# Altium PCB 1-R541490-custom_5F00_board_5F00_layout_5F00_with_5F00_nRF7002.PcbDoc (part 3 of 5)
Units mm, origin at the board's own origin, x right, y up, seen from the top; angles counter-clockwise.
Board outline 180 x 80 mm, 6 copper layers (Top Layer, GND 1, Signal 1, POWER, GND 2, Bottom Layer), stack 1.609 mm thick; 321 components, 275 nets, 828 pads, 1164 vias.
Unrouted connection lines stored in the file: 746.
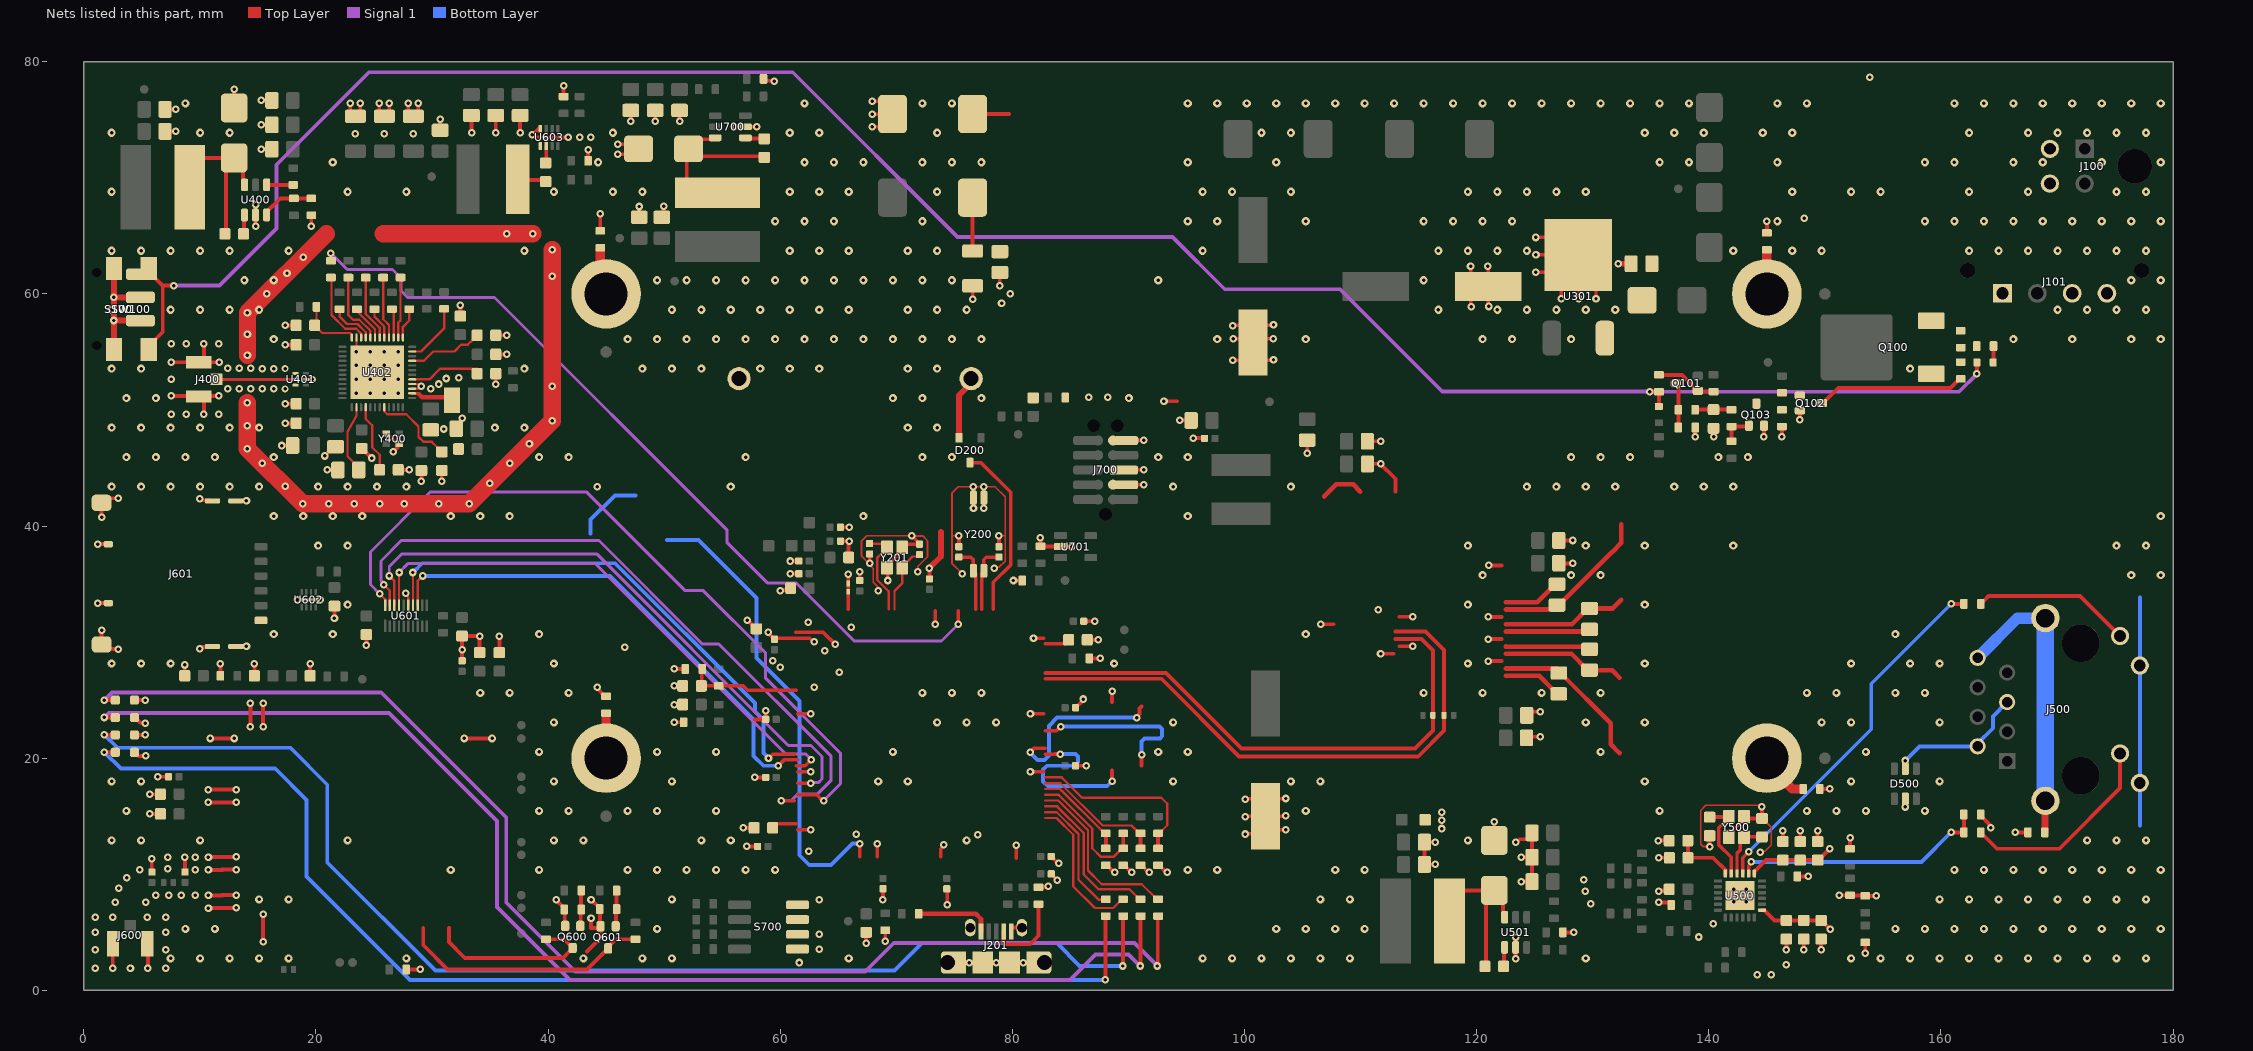
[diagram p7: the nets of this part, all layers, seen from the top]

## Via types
v1: diameter 0.65, hole 0.3, Top Layer to Bottom Layer, tented both sides, 675 vias
v2: diameter 0.7, hole 0.3, Top Layer to Bottom Layer, tented both sides, 462 vias
v3: diameter 0.6, hole 0.3, Top Layer to Bottom Layer, 16 vias
v4: diameter 0.6, hole 0.3, Top Layer to Bottom Layer, tented both sides, 7 vias
v5: diameter 0.6, hole 0.3, Top Layer to Bottom Layer, tented bottom, 4 vias

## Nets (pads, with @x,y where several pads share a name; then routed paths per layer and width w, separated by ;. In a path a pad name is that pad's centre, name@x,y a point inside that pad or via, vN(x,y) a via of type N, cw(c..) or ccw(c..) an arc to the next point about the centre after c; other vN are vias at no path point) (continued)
GND: BT200.1 C100.2 C101.2 C102.1 C103.1 C113.1 C200.1 C201.1 C202.2 C203.2 C204.2 C205.2 C206.1 C207.1 C208.1 C209.1 C210.1 C211.1 C212.1 C213.1 C214.1 C215.1 C216.1 C217.1 C218.1 C219.1 C220.1 C221.1 C222.1 C223.1 C224.1 C225.1 C226.1 C227.1 C228.1 C301.1 C302.2 C303.1 C304.1 C305.1 C306.1 C307.1 C308.1 C309.1 C318.1 C325.1 C401.2 C402.2 C403.1 C404.1 C405.1 C406.1 C407.1 C408.1 C409.1 C410.1 C411.1 C412.1 C413.1 C414.1 C415.1 C416.1 C417.1 C418.1 C419.1 C420.2 C421.1 C422.1 C423.1 C500.1 C501.1 C502.1 C503.1 C504.1 C505.1 C506.1 C507.1 C508.1 C509.1 C510.1 C512.2 C513.2 C514.1 C515.1 C516.1 C600.1 C601.1 C602.2 C603.1 C604.2 C605.1 C606.2 C607.1 C608.2 C609.2 C610.1 C611.1 C612.1 C613.1 C615.2 C616.2 C617.1 C618.1 C619.1 C620.1 C621.1 C701.1 C702.2 C703.2 C704.1 C705.1 C706.1 D106.2 D400.2 D500.2 D501.2 D700.1 D701.1 D702.1 D703.1 D704.2 J100.3 J100.4 J101.3 J101.4 J200.1 J200.2 J201.5 J201.6 J201.7 J201.8 J201.9 J201.10 J201.11 J400.G1 J400.G2 J500.9 J500.11 J600.G1 J600.G2 J601.C5 J601.MH1 J601.MH2 J601.MH3 J601.MH4 J601.MH5 J601.MH6 J601.X1 J601.X2 J700.3 J700.5 J700.9 Q102.2 Q103.2 Q600.2 Q601.2 R108.1 R109.1 R110.1 R111.1 R116.2 R120.1 R200.1 R204.1 R205.2 R208.1 R209.1 R403.1 R513.1 R514.1 R515.1 R520.1 R521.1 R602.1 R603.1 R608.1 R610.1 R615.1 R616.1 R711.1 R712.1 R713.1 R714.1 R720.1 R721.1 R722.1 S100.2 S100.3 S700.5 S700.6 S700.7 S700.8 SW100.1 SW100.2 U301.4 U400.2 U401.2 U401.5 U401.7 U402.27 U402.28 U402.47 U402.49 U500.25 U501.2 U601.15 U602.9 U603.4 U700.2 U701.2 Y200.2 Y200.3 Y201.2 Y201.4 Y400.2 Y400.4 Y500.2 Y500.4 | length 497.3
  Top Layer w0.15: v1(68.443,34.41) 68.372,34.48 68.372,34.817 68.025,35.164 68.025,36.347 67.707,36.665 67.7,36.665 v1(67.7,36.8) 67.606,36.8 67.01,37.396 67.01,38.738 67.447,39.175 71.325,39.175 v1(71.35,39.15) 72.278,39.15 72.69,38.738 72.69,37.346 72.349,37.005 71.856,36.512 71.856,36.056 v1(71.85,36.05) ; v1(75.385,39.157) 74.799,39.157 74.793,39.15 ; v1(75.7,35.9) 74.793,36.807 74.793,39.15 ; v1(78.456,36.35) 78.548,36.442 78.842,36.442 79.377,36.976 79.377,39.15 ; v1(78.84,39.157) 79.37,39.157 79.377,39.15 ; v1(140.064,12.389) 139.511,12.389 139.3,12.6 139.3,15.5 139.738,15.938 144.24,15.938 144.25,15.929 144.482,15.929 v1(144.578,15.833) ; v1(144.446,11.902) 144.529,11.985 144.841,11.985 145.378,12.522 145.378,14.047 144.603,14.822 C510.1@144.578,14.822 ; v1@144.602,11.746 v1@144.685,11.829 ; 74.793,39.15 74.793,42.823 75.352,43.382 v1(76.648,43.382) v1(77.548,43.382) 78.506,43.382 79.377,42.512 79.377,39.15
  Top Layer w0.2: v1(18.375,33.657) U602.9@19.375,33.657 v1(20.375,33.657) ; v3(23.494,55.037) U402.47@23.494,56.237 ; v1(27.743,34.2) 27.743,34.091 27.96,33.875 U601.15@27.96,33.17 ; U402.27@28.294,51.837 28.772,51.837 28.971,52.036 28.769,52.237 U402.28@28.294,52.237 ; v1@29.006,51.95 v1(29.092,52.036)
  Top Layer w0.25: Y400.2@26.138,47.982 Y400.4@27.011,47.11
  Top Layer w0.3: C619.1@22.943,75.3 v1(22.943,76.438) ; C619.1@23.8,75.3 v1(23.8,76.438) ; C620.1@25.443,75.3 v1(25.443,76.438) ; C620.1@26.3,75.3 v1(26.3,76.438) ; C621.1@27.943,75.3 v1(27.943,76.438) ; C621.1@28.8,75.3 v1(28.8,76.438) ; v1(45.992,72.043) D704.2@47.131,72.043 ; v1(45.993,72.9) D704.2@47.131,72.9 ; C211.1@59.5,30.25 59.6,30.35 61.362,30.35 ; 61.501,13.85 v1(62.639,13.85) ; 61.501,18.85 v1(62.639,18.85) ; 61.501,23.85 v1(62.639,23.85) ; 61.501,30.35 62.55,30.35 62.869,30.03 v1(62.95,30.03) ; 65.85,32.838 J200.1@65.85,34.344 J200.2@65.85,35.056 ; J200.2@65.858,35.063 v1@65.858,35.83 ; v1(67.7,36.8) C205.2@67.7,37.59 ; v1(67.925,74.396) 68.873,74.396 D106.2@68.923,74.446 ; v1(67.925,75.496) 68.959,75.496 D106.2@68.973,75.51 ; v1(67.925,76.596) 68.972,76.596 D106.2@68.973,76.595 ; 68.35,11.501 v1(68.35,12.639) ; Y201.4@69.05,36.565 Y201.4@69.2,36.415 69.265,36.35 v1(69.265,35.311) ; Y201.4@69.265,36.65 Y201.2@70.542,37.927 ; Y201.2@70.5,38.09 Y201.2@70.5,38.165 70.775,38.44 C204.2@72,38.44 71.84,38.6 71.84,38.66 v1(71.35,39.15) ; v1(73.35,31.561) 73.35,32.699 ; 73.85,11.501 73.85,12.215 74.1,12.465 v1(74.1,12.56) ; v1(76.575,59.558) C102.1@76.575,60.696 ; v1(78.925,60.708) C103.1@78.925,61.846 ; v1@79.065,59.187 v1(79.065,59.214) ; 80.35,11.362 v1(80.35,12.5) ; v1(81.561,18.85) 82.699,18.85 ; v1(81.561,23.85) 82.699,23.85 ; v1(81.82,30.35) 82.699,30.35 ; J700.3@90.162,43.564 v1(91.3,43.564) ; J700.5@90.162,44.834 v1(91.3,44.834) ; J700.9@90.165,47.374 v1(91.303,47.374) ; v1(93.062,50.743) 94.2,50.743 ; v1(99.003,54.27) 99.033,54.3 102.467,54.3 v1(102.497,54.33) ; v1(99.003,57.27) 99.033,57.3 102.467,57.3 v1(102.497,57.33) ; v1(99.017,56.153) 100.397,56.153 C100.2@100.75,55.8 101.103,56.153 v1(102.483,56.153) ; v1(100.053,13.47) 100.083,13.5 101.8,13.5 102.152,13.852 v1(103.533,13.852) ; v1(100.053,16.47) 100.083,16.5 v1@103.517,16.5 ; v1(100.067,14.97) 100.097,15 C302.2@101.8,15 103.503,15 v1(103.533,15.03) ; C302.2@101.8,16.5 v1@103.517,16.5 ; v1(103.547,16.53) v1@103.517,16.5 ; v1(105.4,46.262) C325.1@105.4,47.4 ; v1(106.567,31.537) 107.705,31.537 ; C308.1@110.59,45.35 v1(111.728,45.35) ; C307.1@110.59,47.3 v1(111.728,47.3) ; v1(111.717,29) 112.855,29 ; 113.35,29.632 v1(114.488,29.632) ; 113.35,32.172 v1(114.488,32.172) ; v1(119.47,62.397) 119.5,62.367 119.5,58.933 v1(119.53,58.903) ; v1(120.97,62.383) 121,62.353 C101.2@121,60.65 121,58.947 v1(121.03,58.917) ; C305.1@124.291,21.757 124.397,21.863 v1(125.47,21.863) ; C306.1@124.307,23.69 124.608,23.99 v1(125.47,23.99) ; v1(125.096,61.862) U301.4@127.393,61.862 ; v1(125.096,64.862) U301.4@127.393,64.862 ; v1(125.11,63.362) U301.4@128.863,63.362 ; U301.4@126.1,60.506 127.324,61.73 127.324,61.93 U301.4@128.765,63.371 ; v1(127.28,59.589) U301.4@127.28,61.73 ; U301.4@127.333,64.888 127.333,64.803 U301.4@128.765,63.371 ; U301.4@128.75,63.386 U301.4@128.765,63.371 ; v1(128.78,59.603) U301.4@128.78,63.356 ; U301.4@129.48,65.953 U301.4@129.599,66.072 ; U301.4@130.25,64.856 U301.4@128.765,63.371 ; v1(130.28,59.589) U301.4@130.28,61.886
  Top Layer w0.33: v1(26.655,46.399) 27.034,46.777 27.034,46.978 27.144,47.088 Y400.4@27.194,47.088
  Top Layer w0.335: v1(1.191,33.36) J601.X1@2.115,33.36 ; v1(1.191,38.44) J601.X2@2.115,38.44 ; J601.MH1@1.535,30.1 v1(1.535,31.024) ; v1(1.535,40.776) J601.MH6@1.535,41.7 ; J601.MH1@2.05,29.4 v1(2.974,29.4) ; J601.MH6@2.05,42.4 v1(2.974,42.4) ; v1(2.5,1.9) 2.5,3.067 J600.G2@2.525,4 ; D702.1@4.366,20.507 4.383,20.507 4.691,20.2 v1(5.346,20.2) ; D703.1@4.366,22.006 v1@5.296,22.006 ; D701.1@4.366,23.508 4.383,23.508 4.831,23.06 5.237,23.06 v1(5.298,23) ; D700.1@4.366,25.008 v1@5.296,25.008 ; J600.G1@5.475,4 5.532,3.067 v1(5.532,1.9) ; v1(5.668,15.202) C607.1@6.6,15.2 ; v1(5.668,16.902) C605.1@6.6,16.9 ; C601.1@5.854,10.306 v1(5.854,11.322) ; v1@6.37,18.4 C603.1@7.3,18.4 ; C405.1@7,74 v1(7.93,74) ; C404.1@7,75.9 v1(7.93,75.9) ; v1(7.544,51.212) 9.869,51.212 J400.G1@9.919,51.162 ; v1(7.544,54.112) 8.786,54.112 ; C612.1@8.7,27.1 v1@8.7,28.03 ; C600.1@8.716,10.453 v1(8.716,11.484) ; J400.G2@9.144,54.47 8.786,54.112 ; J400.G2@9.986,54.112 8.786,54.112 ; v1(10,29.45) 10.085,29.45 10.208,29.573 10.843,29.573 J601.MH2@10.9,29.63 ; v1(10,42.35) 10.085,42.35 10.208,42.228 10.843,42.228 J601.MH5@10.9,42.17 ; v1(10.344,49.637) 10.344,51.212 v1(11.644,51.212) ; J400.G2@10.344,54.47 v1(10.344,55.687) ; J400.G2@10.361,54.112 v1(11.661,54.112) ; v1(10.729,16.2) 11.925,16.2 v1(13.121,16.2) ; v1(10.729,17.3) 11.925,17.3 v1(13.121,17.3) ; v1(10.745,7.084) 11.941,7.084 ; v1(10.745,8.184) 11.941,8.184 ; v1(10.745,10.384) 11.941,10.384 ; v1(10.745,11.484) 11.941,11.484 ; v1(10.9,21.7) 11.925,21.7 v1(12.95,21.7) ; R602.1@11.775,27.199 v1(11.775,28.123) ; 11.925,7.1 v1(13.121,7.1) ; 11.925,8.2 v1(13.121,8.2) ; 11.925,10.4 v1(13.121,10.4) ; 11.925,11.5 v1(13.121,11.5) ; D400.2@12.96,76.695 v1@12.96,77.625 ; J601.MH3@13.095,29.63 v1(14.019,29.63) ; J601.MH4@13.095,42.17 v1(14.019,42.17) ; v1(14.35,22.705) 14.35,23.73 v1(14.35,24.755) ; C611.1@14.7,27.199 v1(14.7,28.123) ; v1@14.8,65.82 v1@14.8,67.68 ; v1@15.278,72.47 C403.1@16.208,72.47 ; v1@15.278,74.57 C402.2@16.208,74.57 ; v1@15.278,76.67 C401.2@16.208,76.67 ; v1(15.45,4.174) 15.45,5.37 v1(15.45,6.566) ; v1(15.45,22.705) 15.45,23.73 v1(15.45,24.755) ; v1@17.064,46.937 C417.1@17.994,46.937 ; v1(17.362,48.839) C416.1@18.294,48.837 ; v1@17.364,50.537 C415.1@18.294,50.537 ; v1@17.364,55.612 C407.1@18.294,55.612 ; v1@17.364,57.287 C406.1@18.294,57.287 ; C610.1@19.5,27.199 v1(19.5,28.123) ; v1(19.6,65.818) R403.1@19.6,66.775 ; v1(20.744,46.037) 21.544,46.837 C418.1@21.694,46.837 ; v1(20.962,44.839) C419.1@21.894,44.837 ; v1(21.6,32.076) C613.1@21.6,33.1 ; C420.2@23.944,46.687 23.969,46.687 v1(24.794,45.862) ; v1(24.35,29.716) C609.2@24.35,30.65 ; C421.1@27.094,44.837 v1@28.024,44.837 ; R603.1@27.775,1.8 v1(28.971,1.8) ; v1@29.094,43.857 C422.1@29.094,44.787 ; C618.1@30.7,74.1 v1(30.702,75.032) ; v1@30.844,43.857 C423.1@30.844,44.787 ; C410.1@32.444,58.087 v1(32.444,59.037) ; v1@32.586,29.334 C608.2@32.586,30.52 v1(34.1,30.52) C604.2@34.1,29.1 ; C602.2@32.6,28.394 v1(32.6,29.334) ; v1(32.779,21.7) 33.975,21.7 v1(35.171,21.7) ; C615.2@33.394,75.376 33.409,75.361 v1(33.409,73.87) ; v1@35.494,52.207 C414.1@35.494,53.137 ; C408.1@35.494,54.787 v1@36.424,54.787 ; C409.1@35.494,56.437 v1@36.424,56.437 ; v1(35.494,73.87) C616.2@35.494,75.376 ; C606.2@35.8,29.1 v1(35.8,30.52) ; v1(37.594,73.87) C617.1@37.594,75.376 ; U603.4@39.2,74.2 39.15,74.2 v1(38.65,73.7) 38.687,73.7 38.909,73.478 v1(41.752,73.478) ; v1(40.7,7.8) 40.7,7.776 41.401,7.075 R608.1@41.401,6.975 41.438,6.938 41.438,5.587 Q600.2@41.476,5.55 ; R615.1@41.338,77.001 v1@41.338,77.932 ; 43.352,3.346 44.526,4.521 Q601.2@44.526,5.524 ; R616.1@43.444,71.476 v1(43.444,72.407) ; v1(43.7,6.2) 43.7,5.368 44.37,5.368 Q601.2@44.526,5.524 ; v1(43.7,7.8) 43.751,7.8 44.451,7.1 R610.1@44.451,7 44.488,6.962 44.488,5.562 Q601.2@44.526,5.524 ; v1(44.225,26.1) 44.285,26.04 44.285,25.94 44.9,25.325 R110.1@45,25.325 ; R111.1@44.5,65.425 v1(44.5,66.9) ; v1@47.131,74.878 C702.2@47.131,75.808 ; C706.1@47.85,66.6 v1(47.85,67.53) ; v1@49.23,74.878 C703.2@49.23,75.808 ; C705.1@49.8,66.6 49.95,66.75 v1(49.95,67.55) ; v1(50.861,23.1) R209.1@51.6,23.1 ; v1(50.861,24.625) C225.1@51.6,24.625 ; v1(50.861,26.225) C224.1@51.6,26.225 ; v1(50.861,27.692) R208.1@51.6,27.692 ; v1@51.33,74.878 C704.1@51.33,75.808 ; v1(56.118,74.402) v1@57.98,74.4 ; v1@56.82,14 C206.1@57.75,14 ; v1@57.12,12.4 C212.1@58.05,12.4 ; v1(57.15,31.9) 57.175,31.9 57.925,31.15 C207.1@57.95,31.15 ; 57.818,23.35 C218.1@58.75,23.35 v1(58.75,24.1) ; v1@57.82,18.35 C219.1@58.75,18.35 ; R722.1@58.558,78.523 58.713,78.368 59.43,78.368 v1(59.49,78.308) ; v1(58.95,30.85) 58.95,30.8 C211.1@59.5,30.25 ; v1(60,34.437) 60.06,34.498 60.618,34.498 C222.1@60.774,34.654 ; v1(60.861,35.899) C221.1@61.6,35.899 ; v1(60.861,36.989) C220.1@61.6,36.989 ; C227.1@65.2,38.7 v1(65.939,38.7) 65.895,38.655 C228.1@65.895,37.29 ; C226.1@65.2,39.9 v1(65.939,39.9) ; C228.1@65.85,37.235 C228.1@65.902,37.288 ; C209.1@66.85,35.311 v1(66.85,36.05) ; v1@67.4,4.07 C223.1@67.4,5 ; v1@68.85,7.82 C213.1@68.85,8.75 ; v1(69.048,4.243) R204.1@69.05,5.175 ; C217.1@72.85,35.45 v1@72.85,36.38 ; C214.1@74.35,8.75 74.388,8.712 v1(74.388,7.371) ; C203.2@75.387,38.225 v1@75.387,39.155 ; v1@76.65,41.52 Y200.3@76.65,42.45 v1@76.65,43.38 ; v1@77.55,41.52 Y200.2@77.55,42.45 v1@77.55,43.38 ; C201.1@78.842,38.225 v1(78.84,39.157) ; J201.5@79.9,5.075 79.9,5.368 79.932,5.4 J201.11@80.825,5.4 ; v1(80.097,35.311) R720.1@80.836,35.311 ; R205.2@82.213,8.862 82.265,8.915 83.06,8.915 v1(83.1,8.955) ; v1(82.417,38.993) R721.1@82.417,38.254 82.432,38.239 84.134,38.239 U701.2@84.149,38.225 ; C202.2@83.349,10.04 83.861,9.528 v1(83.861,9.5) ; C208.1@83.349,11.54 83.954,10.935 v1(83.99,10.935) ; U701.2@84.376,38.225 v1(85.115,38.225) ; C210.1@85.45,19.35 v1@86.38,19.35 ; C216.1@85.45,24.35 86.04,24.94 86.04,25.04 v1(86.1,25.1) ; C215.1@86.15,31.8 v1@87.08,31.8 ; C200.1@86.45,30.2 v1@87.38,30.2 ; R200.1@86.625,28.6 v1(87.557,28.598) ; R713.1@88.05,10.775 88.15,10.775 88.755,10.17 v1(88.81,10.17) ; 88.595,24.85 v1@88.595,25.78 ; R714.1@89.55,10.775 89.65,10.775 90.255,10.17 v1(90.276,10.17) ; R712.1@91.051,10.775 91.151,10.775 91.756,10.17 v1(91.81,10.17) ; R711.1@92.551,10.775 92.651,10.775 93.195,10.23 93.29,10.23 v1(93.35,10.17) ; v1(94.434,49.125) C303.1@95.173,49.125 ; v1(95.584,47.575) C301.1@96.323,47.575 ; v1(111.728,45.35) 113.005,44.073 113.005,42.967 ; v1@116.43,10.847 C516.1@115.5,10.847 C515.1@115.5,12.772 v1@116.43,12.772 ; v1(121.008,28.362) 122.146,28.362 ; v1(121.008,30.267) 122.146,30.267 ; v1(121.008,32.172) 122.146,32.172 ; v1(121.024,36.617) 122.162,36.617 ; D501.2@121.519,13.594 v1@121.519,14.525 ; v1(123.358,12.771) 123.443,12.771 123.69,13.018 124.36,13.018 124.767,13.425 C513.2@124.767,13.569 C512.2@124.767,11.469 ; v1@123.359,2.72 v1(123.361,4.582) ; v1@123.837,9.369 C514.1@124.767,9.369 C512.2@124.767,11.469 ; v1@123.837,11.469 C512.2@124.767,11.469 ; C309.1@127.42,36.803 127.433,36.79 v1(128.294,36.79) ; C304.1@127.42,38.757 v1(128.294,38.757) ; R520.1@127.425,5 v1@128.355,5 ; v1@135.658,12.898 C501.1@136.588,12.898 ; v1(135.671,7.578) 136.596,7.578 136.753,7.42 R514.1@136.753,7.348 ; v1@135.673,11.422 C500.1@136.603,11.422 ; v1(135.678,8.55) 135.738,8.61 136.476,8.61 C508.1@136.588,8.723 ; v1(138.82,47.696) 138.822,47.699 138.822,48.497 R116.2@138.825,48.5 ; C509.1@139.928,13.459 C509.1@140.066,13.321 v1@140.066,12.39 ; v1(140.407,47.696) C113.1@140.407,48.426 ; Y500.2@141.768,13.493 143.125,14.85 143.153,14.822 C510.1@144.578,14.822 v1(144.578,15.833) ; Y500.4@143.028,14.948 Y500.4@143.166,15.086 ; v1(144.75,47.696) Q103.2@144.75,48.645 ; R108.1@145,65.255 v1(145,66.252) ; R120.1@146.297,48.573 146.3,48.57 v1(146.3,47.696) ; C502.1@146.378,12.822 v1@146.378,13.753 ; v1(146.677,3.491) C505.1@146.678,4.422 ; R513.1@147.628,9.822 v1(148.56,9.821) ; v1@147.848,49.149 Q102.2@147.848,49.948 ; C503.1@147.878,12.822 v1(147.88,13.754) ; v1@148.178,3.492 C506.1@148.178,4.422 ; C504.1@149.378,12.822 v1@149.378,13.753 ; R109.1@149.575,17.35 v1(150.427,17.35) ; v1@149.678,3.492 C507.1@149.678,4.422 ; R521.1@163.425,15.15 163.425,15.05 164.24,14.235 164.24,14.083 v1(164.3,14.022) ; v1(166.417,13.611) R515.1@167.492,13.611
  Top Layer w0.35: v1@67.765,76.539 67.867,76.539 v1(67.925,76.596) ; v1@67.85,74.396 v1(67.925,74.396)
  Top Layer w0.5: SW100.1@2.6,55.2 v1(2.6,57.709) ; SW100.2@2.6,62.2 v1(2.6,59.7) ; S100.3@4.875,57.7 4.87,57.705 2.605,57.705 v1(2.6,57.709) ; S100.2@4.875,59.7 v1(2.6,59.7) ; v1(72.848,36.382) 73.85,37.384 73.85,39.5 ; v1(132.2,62.6) C318.1@133.3,62.6 ; v1(2.6,57.709) v1(2.6,59.7)
  Top Layer w1.5: v1(14.1,50.64) v1(14.1,46.677) v1(18.852,41.925) v1(33.214,41.925) v1(40.344,49.055) v1(40.344,63.822) ; v1(14.104,54.719) v1(14.104,58.36) 20.913,65.17 ; 25.79,65.17 v1(38.7,65.17)
  Bottom Layer w0.335: 177.13,14.2 J500.9@177.13,17.875 J500.11@177.13,27.985 177.13,33.85
  other v1: 144.178,1.342 145.378,1.342 1,1.9 4.025,1.9 7.05,1.9 146.675,2.221 80.947,2.391 61.65,2.4 76.298,2.398 78.598,2.398 123.358,2.718 1,3.5 7.05,3.5 148.177,3.491 149.677,3.491 63.35,3.561 67.398,4.068 139.134,4.598 63.35,4.831 1,5 7.05,5 128.357,4.998 140.378,5.722 1,6.3 2.5,6.3 5.475,6.3 7.05,6.3 129.83,7.48 2.716,7.584 5.346,7.584 63.35,7.818 68.848,7.818 6.216,8.184 7.316,8.184 8.416,8.184 9.616,8.184 129.35,8.55 3.016,8.784 123.836,9.371 129.24,9.52 3.716,9.684 4.816,10.384 9.616,10.384 7.235,10.468 116.432,10.846 135.671,11.424 7.234,11.484 9.616,11.484 123.836,11.471 62.46,12 57.118,12.402 116.432,12.771 135.656,12.899 77.033,13.408 66.55,13.45 146.38,13.754 149.38,13.754 56.818,14.002 121.521,14.526 156.93,15.798 57.818,18.352 6.368,18.402 86.382,19.352 5.298,22.004 5.298,25.006 88.593,25.782 62.939,26.1 65.08,27.39 60,27.85 8.702,28.032 59.35,28.414 63.85,29.25 46.6,29.57 87.382,30.198 66.115,31.3 62.4,31.7 87.082,31.798 111.521,32.807 65.85,35.838 76.652,41.518 77.552,41.518 21.094,41.925 23.319,41.925 25.5,41.925 27.619,41.925 30.6,41.925 44.225,43.38 17.35,43.426 34.994,43.705 29.092,43.856 30.843,43.856 28.026,44.836 15.373,45.404 36.693,45.404 17.062,46.939 38.399,47.11 30.994,48.362 14.1,48.658 147.845,49.146 32.594,49.287 7.544,49.637 8.844,49.637 11.644,49.637 17.362,50.539 86.6,51.082 88.225,51.082 15.373,51.819 16.361,51.812 12.406,51.842 13.395,51.834 14.384,51.827 29.894,51.837 40.344,52.036 35.492,52.206 30.566,52.237 7.544,52.637 31.244,52.712 32.294,52.762 15.373,53.57 16.361,53.563 12.406,53.593 13.395,53.585 14.384,53.578 36.426,54.786 17.362,55.614 7.544,55.687 8.844,55.687 11.644,55.687 36.426,56.436 14.104,56.54 17.362,57.289 79.8,59.996 15.75,60.006 40.344,61.512 17.509,61.765 18.894,63.15 36.426,65.17 14.798,65.818 148.229,66.53 14.802,67.682 15.276,72.471 42.721,73.478 43.689,73.478 23.402,73.802 25.902,73.802 28.402,73.802 57.982,74.398 15.276,74.571 47.129,74.876 49.229,74.876 51.329,74.876 15.276,76.671 12.961,77.626 41.339,77.933 153.862,78.685
  other v2: 7.483,2.76 10.023,2.76 12.563,2.76 15.103,2.76 17.643,2.76 27.803,2.76 43.043,2.76 48.123,2.76 50.663,2.76 65.903,2.76 96.383,2.76 98.923,2.76 101.463,2.76 104.003,2.76 106.543,2.76 109.083,2.76 129.403,2.76 152.263,2.76 154.803,2.76 157.343,2.76 159.883,2.76 162.423,2.76 164.963,2.76 167.503,2.76 170.043,2.76 172.583,2.76 175.123,2.76 177.663,2.76 8.753,5.3 11.293,5.3 49.393,5.3 102.733,5.3 105.273,5.3 107.813,5.3 110.353,5.3 156.073,5.3 158.613,5.3 161.153,5.3 163.693,5.3 166.233,5.3 168.773,5.3 171.313,5.3 173.853,5.3 176.393,5.3 178.933,5.3 15.103,7.84 17.643,7.84 50.663,7.84 106.543,7.84 109.083,7.84 159.883,7.84 162.423,7.84 164.963,7.84 167.503,7.84 170.043,7.84 172.583,7.84 175.123,7.84 177.663,7.84 31.613,10.38 39.233,10.38 46.853,10.38 49.393,10.38 51.933,10.38 54.473,10.38 57.013,10.38 59.553,10.38 95.113,10.38 97.653,10.38 107.813,10.38 110.353,10.38 161.153,10.38 163.693,10.38 166.233,10.38 168.773,10.38 171.313,10.38 173.853,10.38 176.393,10.38 178.933,10.38 2.403,12.92 4.943,12.92 10.023,12.92 22.723,12.92 40.503,12.92 43.043,12.92 53.203,12.92 55.743,12.92 76.063,12.92 119.243,12.92 172.583,12.92 175.123,12.92 177.663,12.92 3.673,15.46 39.233,15.46 41.773,15.46 46.853,15.46 49.393,15.46 54.473,15.46 105.273,15.46 135.753,15.46 148.453,15.46 150.993,15.46 153.533,15.46 158.613,15.46 2.403,18 4.943,18 40.503,18 50.663,18 68.443,18 70.983,18 93.843,18 104.003,18 106.543,18 134.483,18 152.263,18 159.883,18 39.233,20.54 49.393,20.54 54.473,20.54 69.713,20.54 92.573,20.54 95.113,20.54 130.673,20.54 153.533,20.54 40.503,23.08 73.523,23.08 76.063,23.08 78.603,23.08 93.843,23.08 129.403,23.08 134.483,23.08 149.723,23.08 152.263,23.08 159.883,23.08 34.153,25.62 36.693,25.62 41.773,25.62 72.253,25.62 74.793,25.62 77.333,25.62 115.433,25.62 120.513,25.62 125.593,25.62 130.673,25.62 148.453,25.62 150.993,25.62 156.073,25.62 158.613,25.62 2.403,28.16 4.943,28.16 7.483,28.16 40.503,28.16 88.763,28.16 119.243,28.16 134.483,28.16 152.263,28.16 157.343,28.16 159.883,28.16 16.373,30.7 21.453,30.7 39.233,30.7 105.273,30.7 156.073,30.7 22.723,33.24 119.243,33.24 134.483,33.24 120.513,35.78 128.133,35.78 130.673,35.78 176.393,35.78 178.933,35.78 20.183,38.32 22.723,38.32 119.243,38.32 129.403,38.32 134.483,38.32 142.103,38.32 175.123,38.32 177.663,38.32 16.373,40.86 18.913,40.86 21.453,40.86 23.993,40.86 31.613,40.86 34.153,40.86 36.693,40.86 67.173,40.86 95.113,40.86 178.933,40.86 2.403,43.4 4.943,43.4 7.483,43.4 10.023,43.4 12.563,43.4 15.103,43.4 20.183,43.4 22.723,43.4 25.263,43.4 27.803,43.4 55.743,43.4 93.843,43.4 104.003,43.4 124.323,43.4 126.863,43.4 129.403,43.4 131.943,43.4 137.023,43.4 139.563,43.4 142.103,43.4 3.673,45.94 6.213,45.94 8.753,45.94 11.293,45.94 16.373,45.94 39.233,45.94 41.773,45.94 57.013,45.94 72.253,45.94 74.793,45.94 92.573,45.94 95.113,45.94 128.133,45.94 130.673,45.94 133.213,45.94 140.833,45.94 143.373,45.94 2.403,48.48 4.943,48.48 7.483,48.48 10.023,48.48 12.563,48.48 15.103,48.48 35.423,48.48 37.963,48.48 70.983,48.48 73.523,48.48 3.673,51.02 6.213,51.02 69.713,51.02 72.253,51.02 77.333,51.02 90.033,51.02 2.403,53.56 4.943,53.56 37.963,53.56 48.123,53.56 50.663,53.56 53.203,53.56 58.283,53.56 60.823,53.56 63.363,53.56 70.983,53.56 73.523,53.56 157.343,53.56 16.373,56.1 46.853,56.1 49.393,56.1 51.933,56.1 54.473,56.1 57.013,56.1 59.553,56.1 62.093,56.1 64.633,56.1 67.173,56.1 69.713,56.1 72.253,56.1 74.793,56.1 77.333,56.1 97.653,56.1 105.273,56.1 120.513,56.1 123.053,56.1 128.133,56.1 166.233,56.1 171.313,56.1 176.393,56.1 178.933,56.1 2.403,58.64 7.483,58.64 10.023,58.64 12.563,58.64 15.103,58.64 50.663,58.64 53.203,58.64 55.743,58.64 58.283,58.64 60.823,58.64 63.363,58.64 65.903,58.64 70.983,58.64 73.523,58.64 76.063,58.64 116.703,58.64 121.783,58.64 124.323,58.64 126.863,58.64 129.403,58.64 131.943,58.64 170.043,58.64 172.583,58.64 175.123,58.64 177.663,58.64 13.833,61.18 16.373,61.18 49.393,61.18 51.933,61.18 54.473,61.18 57.013,61.18 59.553,61.18 62.093,61.18 64.633,61.18 67.173,61.18 69.713,61.18 72.253,61.18 74.793,61.18 92.573,61.18 115.433,61.18 176.393,61.18 178.933,61.18 2.403,63.72 4.943,63.72 7.483,63.72 10.023,63.72 12.563,63.72 17.643,63.72 37.963,63.72 60.823,63.72 63.363,63.72 65.903,63.72 70.983,63.72 73.523,63.72 96.383,63.72 116.703,63.72 119.243,63.72 121.783,63.72 124.323,63.72 142.103,63.72 147.183,63.72 149.723,63.72 162.423,63.72 164.963,63.72 167.503,63.72 170.043,63.72 172.583,63.72 175.123,63.72 177.663,63.72 59.553,66.26 62.093,66.26 64.633,66.26 72.253,66.26 95.113,66.26 97.653,66.26 105.273,66.26 115.433,66.26 117.973,66.26 120.513,66.26 123.053,66.26 145.913,66.26 158.613,66.26 161.153,66.26 163.693,66.26 166.233,66.26 168.773,66.26 171.313,66.26 173.853,66.26 176.393,66.26 178.933,66.26 2.403,68.8 22.723,68.8 27.803,68.8 40.503,68.8 45.583,68.8 48.123,68.8 60.823,68.8 63.363,68.8 65.903,68.8 73.523,68.8 96.383,68.8 98.923,68.8 104.003,68.8 119.243,68.8 121.783,68.8 124.323,68.8 126.863,68.8 129.403,68.8 147.183,68.8 152.263,68.8 154.803,68.8 162.423,68.8 167.503,68.8 175.123,68.8 177.663,68.8 21.453,71.34 44.313,71.34 62.093,71.34 64.633,71.34 67.173,71.34 72.253,71.34 74.793,71.34 77.333,71.34 95.113,71.34 102.733,71.34 135.753,71.34 138.293,71.34 145.913,71.34 158.613,71.34 161.153,71.34 166.233,71.34 168.773,71.34 173.853,71.34 178.933,71.34 2.403,73.88 10.023,73.88 12.563,73.88 45.583,73.88 60.823,73.88 63.363,73.88 73.523,73.88 101.463,73.88 104.003,73.88 134.483,73.88 137.023,73.88 139.563,73.88 144.643,73.88 147.183,73.88 162.423,73.88 167.503,73.88 170.043,73.88 172.583,73.88 175.123,73.88 177.663,73.88 8.753,76.42 62.093,76.42 72.253,76.42 74.793,76.42 95.113,76.42 97.653,76.42 100.193,76.42 102.733,76.42 105.273,76.42 107.813,76.42 110.353,76.42 112.893,76.42 115.433,76.42 117.973,76.42 120.513,76.42 123.053,76.42 125.593,76.42 128.133,76.42 130.673,76.42 133.213,76.42 135.753,76.42 138.293,76.42 145.913,76.42 148.453,76.42 161.153,76.42 163.693,76.42 166.233,76.42 168.773,76.42 171.313,76.42 173.853,76.42 176.393,76.42 178.933,76.42
  other v3: 23.494,51.437 24.694,51.437 25.894,51.437 27.094,51.437 23.494,52.637 24.694,52.637 25.894,52.637 27.094,52.637 23.494,53.837 24.694,53.837 25.894,53.837 27.094,53.837 24.694,55.037 25.894,55.037 27.094,55.037
  other v4: 17.35,51.812 19.694,52.637 17.35,53.556
  other v5: 142.128,7.622 143.228,7.622 142.128,8.722 143.228,8.722
HOLD:  | length 15
  Top Layer w0.3: 82.838,22.35 83.782,22.35 83.8,22.368
  Top Layer w0.335: 83.8,22.368 84.132,22.7 v1(84.15,22.7) ; 91.135,19.35 v1@91.135,20.28
  Bottom Layer w0.335: v1(84.15,22.7) 84.178,22.728 84.622,22.728 84.623,22.73 92.674,22.73 92.9,22.504 92.9,21.896 92.704,21.7 91.4,21.7 91.133,21.433 v1(91.133,20.282)
I2C2_SCL: R300.2 | length 49.8
  Top Layer w0.335: 82.838,26.85 92.85,26.85 99.536,20.164 114.964,20.164 117.175,22.375 117.175,29.325 115.598,30.902 113.005,30.902
I2C2_SDA: R301.2 | length 47.3
  Top Layer w0.335: 82.838,27.35 93.25,27.35 99.755,20.845 114.685,20.845 116.225,22.385 116.225,29.291 115.242,30.275 113.012,30.275 113.005,30.267 112.99,30.253
I2S2_CK: 
I2S2_MCK: 
I2S2_SDO: 
I2S2_WS:  | length 3.8
  Top Layer w0.335: 61.362,30.85 63.7,30.85 v1(64.75,29.8)
ID1: R700.1 R711.2 | length 15.7
  Top Layer w0.2: 82.838,18.35 84.25,18.35 86,16.6 92.835,16.6 93.35,16.085 93.35,14.224 92.651,13.525 R700.1@92.551,13.525
  Top Layer w0.335: R711.2@92.551,12.225 R700.1@92.551,13.525
ID2: R701.1 R712.2 | length 11.3
  Top Layer w0.2: 82.838,17.85 84.129,17.85 87.779,14.2 90.276,14.2 90.951,13.525 R701.1@91.051,13.525
  Top Layer w0.335: R712.2@91.051,12.225 R701.1@91.051,13.525
ID3: R702.1 R713.2 | length 8.1
  Top Layer w0.2: 82.838,17.35 84.105,17.35 87.625,13.83 87.645,13.83 87.95,13.525 R702.1@88.05,13.525
  Top Layer w0.335: R713.2@88.05,12.225 R702.1@88.05,13.525
ID4: R703.1 R714.2 | length 11.5
  Top Layer w0.2: 82.838,16.85 83.983,16.85 86.89,13.943 86.89,12.235 87.625,11.5 88.725,11.5 89.45,12.225 R714.2@89.55,12.225
  Top Layer w0.335: R714.2@89.55,12.225 R703.1@89.55,13.525
"Input Voltage(ADC/IO)": C224.2 R206.1 R208.2 | length 9.8
  Top Layer w0.3: R208.2@53.275,27.692 53.237,27.654 53.237,26.263 C224.2@53.2,26.225 R206.1@54.7,26.225 56.818,26.225 57.193,25.85 61.362,25.85
IRQ: R407.2 | length 71.6
  Top Layer w0.2: R407.2@21.294,62.862 v1(21.294,63.512)
  Top Layer w0.3: v1(75.35,31.561) 75.35,32.699
  Signal 1 w0.256: v1(21.294,63.512) 22.706,62.1 26.594,62.1 27.313,61.381 27.313,60.287 27.9,59.7 35.387,59.7 55.4,39.687 55.4,38.6 58.888,35.112 61.362,35.112 66.374,30.1 73.889,30.1 v1(75.35,31.561)
LED1: R708.1 | length 15.3
  Top Layer w0.2: 82.838,16.35 83.96,16.35 86.52,13.79 86.52,10.33 87.7,9.15 91.151,9.15 92.451,7.85 R708.1@92.551,7.85
LED2: R709.1 | length 13.6
  Top Layer w0.2: 82.838,15.85 83.855,15.85 86.15,13.555 86.15,9.993 87.427,8.716 90.085,8.716 90.951,7.85 R709.1@91.051,7.85
LED3: R710.1 | length 10.6
  Top Layer w0.2: 82.838,15.35 83.831,15.35 85.7,13.481 85.7,9.532 87.414,7.818 R710.1@88.048,7.818
LED4: R715.1 | length 12.8
  Top Layer w0.2: 82.838,14.85 83.808,14.85 85.25,13.408 85.25,8.955 87.112,7.093 88.691,7.093 89.448,7.85 R715.1@89.548,7.85
LEDA: R518.1 R521.2 U500.2 | length 22
  Top Layer w0.3: U500.2@143.428,10.072 143.428,10.738 143.668,10.978 v1(143.668,11.072)
  Top Layer w0.335: v1(160.9,13.611) R518.1@161.975,13.611 R521.2@161.975,15.15
  Bottom Layer w0.335: v1(143.668,11.072) 158.322,11.072 v1@160.87,13.62
LEDB: R519.1 U500.3 | length 31.7
  Top Layer w0.3: U500.3@142.928,10.072 142.928,11.203 142.934,11.209 142.934,11.434 v1(143.428,11.928)
  Top Layer w0.335: v1(160.9,33.3) R519.1@161.975,33.3
  Bottom Layer w0.3: v1(143.428,11.928) 154,22.5 154,26.4 v1(160.9,33.3)
"MAIN UART CTS": U601.17 | length 47.2
  Top Layer w0.2: U601.17@27.16,33.17 v1(27.16,36)
  Top Layer w0.3: 61.362,19.35 62.14,19.35 v1(62.676,19.886)
  Signal 1 w0.256: v1(27.16,36) 27.92,36.76 44.08,36.76 60.49,20.35 62.213,20.35 v1(62.676,19.886)
"MAIN UART DCD": U601.19 | length 59.6
  Top Layer w0.2: v1(25.85,34.95) 26.36,34.44 U601.19@26.36,33.17
  Top Layer w0.3: v1(60.085,16.35) 61.223,16.35
  Signal 1 w0.256: v1(25.85,34.95) 25.85,35.057 25.666,35.241 25.666,35.256 25.6,35.322 25.6,37 27.347,38.747 44.378,38.747 53.275,29.85 54.703,29.85 64.393,20.16 64.393,18.093 63.2,16.9 61.5,16.9 60.95,16.35 v1(60.085,16.35)
"MAIN UART RI": U601.20 | length 65.5
  Top Layer w0.2: v1(25.5,34.15) 25.96,33.69 U601.20@25.96,33.17
  Top Layer w0.3: 61.501,16.85 63.146,16.85 63.646,16.35 v1(63.741,16.35)
  Signal 1 w0.256: v1(25.5,34.15) 24.694,34.956 24.694,37.776 29.869,42.95 43.296,42.95 51.808,34.437 53.373,34.437 58.747,29.063 58.747,26.889 65.2,20.436 65.2,17.809 v1(63.741,16.35)
"MAIN UART RTS": U601.18 | length 52.7
  Top Layer w0.2: v1(26.317,35.7) 26.76,35.257 U601.18@26.76,33.17
  Top Layer w0.3: 61.501,17.85 v1(62.639,17.85)
  Signal 1 w0.256: v1(26.317,35.7) 26.317,36.517 27.411,37.611 44.189,37.611 60.7,21.1 62.65,21.1 63.6,20.15 63.6,18.2 63.325,17.925 62.715,17.925 v1(62.639,17.85)
"MAIN UART RXD": U601.13 | length 43.8
  Top Layer w0.2: U601.13@28.76,33.17 28.76,35.257 v1(29.203,35.7)
  Top Layer w0.3: v1(59.825,19.35) 59.829,19.35 60.329,19.85 61.501,19.85
  Bottom Layer w0.335: v1(29.203,35.7) 45.32,35.7 57.7,23.32 57.7,20.2 58.55,19.35 v1(59.825,19.35)
"MAIN UART TXD": U601.14 | length 45.2
  Top Layer w0.2: U601.14@28.36,33.17 v1(28.36,36)
  Top Layer w0.3: v1(58.99,20) 59.341,20.35 61.223,20.35
  Bottom Layer w0.335: v1(28.36,36) 29.16,36.8 45.781,36.8 57.818,24.763 57.818,24.043 58.55,23.311 58.55,20.457 58.99,20.017 v1(58.99,20)
Mamp_rf: 
MIC_on:  | length 40.9
  Top Layer w0.3: 66.85,11.501 v1(66.85,12.639)
  Bottom Layer w0.335: 50.25,38.798 52.952,38.798 57.95,33.8 57.95,28.624 61.65,24.924 61.65,11.64 62.5,10.79 64.39,10.79 66.239,12.639 v1(66.85,12.639)
MISO:  | length 15.1
  Top Layer w0.3: 81.876,20.832 81.894,20.85 82.838,20.85
  Top Layer w0.335: v1(81.526,20.5) 81.544,20.5 81.876,20.832 ; v1(90.72,23.5) 90.72,23.585 90.952,23.818 90.952,24.267 91.135,24.45
  Bottom Layer w0.335: v1(81.526,20.5) 82.176,19.85 82.771,19.85 83.15,20.229 83.15,22.789 83.861,23.5 v1(90.72,23.5)
MOSI:  | length 14.9
  Top Layer w0.3: 82.838,20.35 83.66,20.35
  Top Layer w0.335: 83.66,20.35 v1(84.115,20.35) ; v1@88.595,18.02 88.595,18.95
  Bottom Layer w0.335: v1(84.115,20.35) 85.454,20.35 85.65,20.154 85.65,19.65 85.352,19.352 82.967,19.352 82.65,19.034 82.65,18 83.05,17.6 88.179,17.6 v1(88.597,18.018)
MUTE: 
NetBT200_2: BT200.2 D200.2 | length 5.5
  Top Layer w0.5: D200.2@75.4,47.611 75.4,51.275 76.45,52.324 BT200.2@76.45,52.7
NetC102_2: C102.2 C103.2 D103.1 | length 4.6
  Top Layer w0.335: C102.2@76.575,63.696 D103.1@76.575,68.296
NetC104_1: D106.1 | length 3.2
  Top Layer w0.335: D106.1@76.575,75.496 79.73,75.496
NetC104_2: 
NetC106_2: 
NetC110_2: 
NetC111_2: 
NetC112_2: 
NetC113_2: C113.2 R118.1 R123.2 | length 3.1
  Top Layer w0.335: R118.1@138.825,50.026 C113.2@140.407,50.026 R123.2@141.96,50.026
NetC200_2: C200.2 | length 2.2
  Top Layer w0.3: 82.838,29.85 84.525,29.85 84.85,30.175 C200.2@84.85,30.2
NetC201_2: C201.2 Y200.1 | length 5.7
  Top Layer w0.3: 77.35,32.838 77.35,35.95 Y200.1@77.55,36.15 77.55,37.108 77.766,37.325 C201.2@78.842,37.325
NetC203_1: C203.1 Y200.4 | length 5.7
  Top Layer w0.3: C203.1@75.387,37.325 76.426,37.325 76.65,37.1 Y200.4@76.65,36.15 76.85,35.95 76.85,32.838
NetC204_1: C204.1 Y201.1 | length 5.9
  Top Layer w0.2: 69.85,32.838 69.85,34.411 70.5,35.061 Y201.1@70.5,36.415 70.5,36.49 71.39,37.38 71.84,37.38 C204.1@72,37.54
NetC205_1: C205.1 Y201.3 | length 7.7
  Top Layer w0.2: C205.1@67.7,38.49 68.875,38.49 Y201.3@69.2,38.165 69.2,38.09 68.35,37.24 68.35,35.374 69.35,34.374 69.35,32.838
NetC206_2: C206.2 | length 2.2
  Top Layer w0.3: C206.2@59.35,14 59.35,14.025 59.675,14.35 61.362,14.35
NetC312_1: C312.1 | length 10.7
  Top Layer w0.4: 122.491,28.997 128.167,28.997 129.575,27.59 C312.1@129.725,27.59 131.662,27.59 132.307,26.945
NetC312_2: C312.2 | length 7.3
  Top Layer w0.4: 122.491,29.632 122.507,29.616 129.498,29.616 C312.2@129.725,29.39
NetC313_1: C313.1 | length 13.6
  Top Layer w0.4: 122.491,27.727 C313.1@126.925,27.727 ; C313.1@127.075,27.34 127.225,27.34 131.557,23.008 131.557,21.195 132.307,20.445
NetC313_2: C313.2 | length 5.1
  Top Layer w0.4: 122.491,27.092 125.377,27.092 126.55,25.92 126.55,25.915 126.92,25.545 C313.2@126.925,25.545
NetC317_1: C317.1 | length 13.8
  Top Layer w0.4: 122.491,32.807 C317.1@126.925,32.807 ; C317.1@126.925,33.19 127.075,33.19 131.681,37.796 131.707,37.796 132.457,38.546 132.457,40.146
NetC317_2: C317.2 | length 5.1
  Top Layer w0.4: 122.491,33.442 125.227,33.442 126.775,34.99 C317.2@126.925,34.99
NetC318_2: C318.2 D300.1 U301.3
NetC321_1: C321.1 | length 10.8
  Top Layer w0.4: 122.491,31.537 128.21,31.537 129.575,32.902 C321.1@129.725,32.902 131.714,32.902 132.457,33.646
NetC321_2: C321.2 | length 7.3
  Top Layer w0.4: 122.491,30.902 122.507,30.918 129.541,30.918 C321.2@129.725,31.102
NetC322_1:  | length 3.8
  Top Layer w0.4: 106.867,42.552 107.905,43.59 109.352,43.59 109.975,42.967
NetC322_2: 
NetC323_2: 
NetC324_1: 
NetC324_2: 
NetC326_1: 
NetC400_1: C400.1 D400.1 L400.1 U400.6 | length 15.3
  Top Layer w0.335: L400.1@9.108,69.07 9.108,70.562 10.266,71.719 D400.1@12.96,71.719 ; C400.1@12.16,65.17 12.241,65.251 12.241,71.001 D400.1@12.96,71.719 ; U400.6@13.85,69.45 13.724,69.576 13.724,70.956 D400.1@12.96,71.719
NetC400_2: C400.2 U400.1 | length 1.6
  Top Layer w0.335: C400.2@13.76,65.17 13.805,65.215 13.805,66.705 U400.1@13.85,66.75
NetC406_2: C406.2 R402.1 U402.48 | length 5.4
  Top Layer w0.2: R402.1@20.044,58.887 20.044,57.26 19.983,57.199 20.544,56.637 22.944,56.637 23.094,56.487 U402.48@23.094,56.237
NetC409_2: C409.2 U402.33 | length 6.5
  Top Layer w0.2: U402.33@28.294,54.237 29.301,54.237 30.107,55.043 31.936,55.043 32.506,55.612 33.069,55.612 33.494,56.037 33.496,56.037 33.894,56.435 C409.2@33.894,56.437
NetC414_2: C414.2 U402.29 | length 6
  Top Layer w0.2: U402.29@28.294,52.637 29.794,52.637 30.72,53.563 C414.2@33.894,53.563
NetC419_2: C419.2 U402.14 | length 6
  Top Layer w0.2: U402.14@23.494,50.237 23.494,49.487 22.719,48.109 22.719,46.013 23.219,45.513 23.219,45.502 23.694,45.027 C419.2@23.694,44.837
NetC421_2: C421.2 U402.16 | length 5.9
  Top Layer w0.2: U402.16@24.294,50.237 24.294,49.23 24.844,48.68 24.844,46.788 25.494,46.138 C421.2@25.494,44.837
NetC423_2: C423.2 U402.20 | length 7.3
  Top Layer w0.2: U402.20@25.894,50.237 25.894,49.892 26.149,49.637 27.789,49.637 28.844,48.582 28.844,47.675 29.256,47.263 29.969,47.263 30.444,46.787 30.444,46.785 C423.2@30.844,46.387 C423.2@30.844,46.387
NetC500_2: C500.2 C501.2 U500.6 | length 5.4
  Top Layer w0.335: C501.2@138.188,12.898 138.196,12.89 138.196,11.43 C500.2@138.203,11.422 140.363,11.422 141.428,10.357 U500.6@141.428,10.072
NetC502_2: C502.2 C503.2 C504.2 C505.2 C506.2 C507.2 D500.5 FB500.1 J500.2 J500.5 R504.1 R505.1 R506.2 R507.2 U500.1 U500.19 | length 30.3
  Top Layer w0.335: U500.1@143.928,10.072 143.928,10.238 143.963,10.273 144.913,11.222 C502.2@146.378,11.222 C503.2@147.878,11.222 C504.2@149.378,11.222 ; U500.19@144.578,6.923 144.743,6.923 145.643,6.022 C505.2@146.678,6.022 C506.2@148.178,6.022 C507.2@149.678,6.022 149.703,6.022 v1@150.453,5.272 ; C504.2@149.677,11.455 v1@150.427,12.205 ; v1(151.246,8.199) R504.1@152.178,8.197 152.207,8.169 153.449,8.169 R507.2@153.478,8.14 v1@154.408,8.14 ; R505.1@152.178,12.197 v1(152.18,13.129) ; v1@153.478,3.21 R506.2@153.478,4.14
  Bottom Layer w0.335: v1(156.933,19.802) 158.156,21.025 J500.2@163.16,21.025 163.16,21.265 164.475,22.58 164.475,23.61 J500.5@165.7,24.835
  other v1: 153.477,3.208 150.452,5.271 154.41,8.138 150.428,12.203 117,13.943 117,14.643 117,15.343
NetC509_2: C509.2 U500.5 Y500.1 | length 7.3
  Top Layer w0.3: Y500.1@141.728,14.873 140.866,14.01 140.866,12.522 141.928,11.46 U500.5@141.928,10.072
  Top Layer w0.335: C509.2@140.066,14.921 141.68,14.921 Y500.1@141.728,14.873
NetC510_2: C510.2 U500.4 Y500.3 | length 4.9
  Top Layer w0.3: U500.4@142.428,10.072 142.428,11.822 142.728,12.122 142.728,12.898 Y500.3@143.028,13.198 143.053,13.222 C510.2@144.578,13.222
NetC511_1: C511.1 D501.1 L500.1 U501.6 | length 15.3
  Top Layer w0.335: L500.1@117.667,5.969 117.667,7.462 118.825,8.619 D501.1@121.519,8.619 ; C511.1@120.719,2.069 120.8,2.151 120.8,7.901 D501.1@121.519,8.619 ; U501.6@122.409,6.35 122.283,6.476 122.283,7.856 D501.1@121.519,8.619
NetC511_2: C511.2 U501.1 | length 1.6
  Top Layer w0.335: C511.2@122.319,2.069 122.364,2.115 122.364,3.605 U501.1@122.409,3.65
NetC614_1: C614.1 L600.1 U603.5 | length 2.4
  Top Layer w0.335: L600.1@37.394,69.876 38.226,69.807 39.461,69.807 C614.1@39.794,69.676
NetC614_2: C614.2 U603.6 | length 1.5
  Top Layer w0.3: C614.2@39.794,71.276 39.844,71.601 U603.6@39.844,72.736
NetC700_1: C700.1 D704.1 L700.1 U700.6 | length 15.3
  Top Layer w0.335: D704.1@52.081,72.56 52.844,73.324 54.224,73.324 U700.6@54.35,73.45 ; L700.1@54.6,68.725 53.108,68.725 51.95,69.882 51.95,72.577 52.669,71.858 58.419,71.858 C700.1@58.5,71.777
NetC700_2: C700.2 U700.1 | length 1.6
  Top Layer w0.335: U700.1@57.05,73.45 57.095,73.405 58.585,73.405 C700.2@58.63,73.36
NetC801_1: 
NetC801_2: 
NetC802_1: 
NetC802_2: 
NetC803_1: 
NetC803_2: 
NetC804_1: 
NetC804_2: 
NetC806_1: 
NetC807_1: 
NetC808_1: 
NetC808_2:  | length 5.9
  Bottom Layer w0.335: 43.655,39.35 43.655,40.555 45.75,42.65 47.53,42.65
NetC809_2: 
NetC810_1: 
NetC810_2: 
NetC814_2: 
NetD105_1: D105.1 D107.1 R117.1 S100.1 SW100.3 SW100.4 | length 190.3
  Top Layer w0.335: S100.1@4.875,61.7 5.625,61.7 5.907,61.418 6.094,61.418 6.8,60.712 ; SW100.3@5.6,55.2 5.6,55.5 6.8,56.7 6.8,60.712 ; v1(7.757,60.712) 6.8,60.712 ; v1@134.914,51.587 135.712,51.587 R117.1@135.7,51.575 D105.1@135.7,50.3 ; v1(163.1,53.114) D107.1@163.1,53.819
  Signal 1 w0.335: v1(7.757,60.712) 11.685,60.712 16.6,65.627 16.6,71.132 24.568,79.1 61.076,79.1 75.276,64.9 93.8,64.9 98.3,60.4 108.228,60.4 117.038,51.59 v1(134.911,51.59) ; v1@134.911,51.575 161.561,51.575 v1(163.1,53.114)
NetD107_2: D107.2 R112.1 | length 1.4
  Top Layer w0.335: D107.2@164.5,54.1 164.513,54.113 164.513,55.488 R112.1@164.525,55.5
NetD200_3: D200.3 | length 15.3
  Top Layer w0.3: D200.3@76.35,45.461 77.3,45.461 79.85,42.911 79.85,36.649 78.35,35.149 78.35,32.838
NetD700_2: D700.2 R708.2 | length 112.3
  Top Layer w0.335: v1@1.785,25.008 D700.2@2.716,25.008 ; v1(92.5,2.1) 92.525,2.125 92.525,6.375 R708.2@92.551,6.4
  Signal 1 w0.335: v1(1.784,25.01) 2.423,25.649 25.631,25.649 36.4,14.88 36.4,7.564 42.364,1.6 67.314,1.6 69.782,4.068 90.532,4.068 v1(92.5,2.1)
NetD701_2: D701.2 R709.2 | length 109.8
  Top Layer w0.335: v1@1.785,23.508 D701.2@2.716,23.508 ; v1(91,2.1) 91.025,2.125 91.025,6.375 R709.2@91.051,6.4
  Signal 1 w0.35: v1(1.784,23.509) 2.175,23.9 26.3,23.9 35.611,14.589 35.611,7.189 41.9,0.9 84.95,0.9 87.15,3.1 90,3.1 v1(91,2.1)
NetD702_2: D702.2 R710.2 | length 104.6
  Top Layer w0.335: v1@1.785,20.507 D702.2@2.716,20.507 ; v1(88,0.9) 88.025,0.925 88.025,6.375 R710.2@88.05,6.4
  Bottom Layer w0.335: v1(1.784,20.509) 3.193,19.1 16.5,19.1 19.2,16.4 19.2,9.817 28.117,0.9 v1(88,0.9)
NetD703_2: D703.2 R715.2 | length 107.1
  Top Layer w0.335: v1@1.785,22.006 D703.2@2.716,22.006 ; v1(89.498,2.1) 89.523,2.125 89.523,6.375 R715.2@89.548,6.4
  Bottom Layer w0.335: v1(1.784,22.007) 2.891,20.9 17.796,20.9 20.979,17.717 20.979,11.017 30.296,1.7 69.85,1.7 72.218,4.068 83.832,4.068 85.8,2.1 v1(89.498,2.1)
NetH5_1: H5.1 R108.2 | length 3.7
  Top Layer w0.8: H5.1@145,60 R108.2@145,63.7
NetH6_1: H6.1 R109.2 | length 4.4
  Top Layer w0.8: H6.1@145,20 145,19.533 147.183,17.35 R109.2@148,17.35
NetH7_1: H7.1 R110.2 | length 3.8
  Top Layer w0.8: H7.1@45,20 R110.2@45,23.75
NetH8_1: H8.1 R111.2 | length 4
  Top Layer w0.8: R111.2@44.49,63.8 44.49,60.51 H8.1@45,60
NetJ101_1: J101.1 Q100.2 R100.2
NetJ201_1: J201.1 R202.2 | length 6.6
  Top Layer w0.4: R202.2@71.925,6.6 76.85,6.6 77.3,6.15 J201.1@77.3,5.075
NetJ201_4: J201.4 R205.1 | length 7
  Top Layer w0.335: J201.4@79.25,5.075 79.25,4.171 79.446,3.975 81.517,3.975 82.25,4.708 R205.1@82.25,7.425
NetJ400_1: J400.1 U401.6 | length 6.8
  Top Layer w0.25: J400.1@11.444,52.637 U401.6@18.244,52.637
NetJ500_8: J500.8 J500.13 J500.14 R515.2 | length 25.7
  Top Layer w0.6: R515.2@168.942,13.611 168.967,13.636 168.967,16.292 J500.13@169,16.325
  Bottom Layer w1: J500.8@163.16,28.645 166.59,32.075 J500.14@169,32.075
  Bottom Layer w1.5: J500.13@169,16.325 J500.14@169,32.075
NetJ500_10: J500.10 R518.2 | length 17.8
  Top Layer w0.335: R518.2@163.425,13.611 163.425,13.511 163.582,13.354 163.682,13.354 164.839,12.197 170.2,12.197 175.43,17.427 J500.10@175.43,20.415
NetJ500_12: J500.12 R519.2 | length 13.8
  Top Layer w0.335: R519.2@163.425,33.3 163.425,33.4 163.582,33.557 163.682,33.557 164.093,33.968 171.987,33.968 J500.12@175.43,30.525
NetL100_2: 
NetL401_1: L401.1 U402.26 | length 3.5
  Top Layer w0.254: U402.26@28.294,51.437 28.822,51.437
  Top Layer w0.4: 28.882,51.367 29.162,51.087 31.518,51.087 L401.1@31.594,50.887
NetQ100_1: Q100.1 R100.1 R107.2 R112.2
NetQ101_1: Q101.1 R106.1 R117.2 | length 5.3
  Top Layer w0.335: R117.2@135.7,53.025 137.675,53.025 138.772,51.928 138.772,51.832 Q101.1@138.954,51.65 ; Q101.1@139.05,51.65 139.081,51.619 140.376,51.619 R106.1@140.407,51.587
NetQ101_3: Q101.3 R116.1 R118.2 | length 3.9
  Top Layer w0.335: Q101.3@137.15,52.3 137.193,52.3 137.375,52.118 R118.2@137.375,50.026 R116.1@137.375,48.5
NetQ102_1: Q102.1 Q103.3 R113.1 R120.2
NetQ102_3: Q102.3 R107.1 | length 12.8
  Top Layer w0.335: Q102.3@149.75,50.6 149.85,50.6 151.15,51.9 160.825,51.9 161.6,52.675 R107.1@161.7,52.675
NetQ103_1: Q103.1 R119.1 R123.1 | length 2.9
  Top Layer w0.335: R119.1@141.959,47.3 R123.1@141.96,48.576 141.972,48.563 143.537,48.563 Q103.1@143.55,48.55
NetQ600_1: Q600.1 R607.2 R608.2 | length 3.1
  Top Layer w0.335: Q600.1@42.776,5.55 42.813,5.587 42.813,6.938 R608.2@42.851,6.975 R607.2@42.851,8.6 R607.2@42.826,8.625
NetQ600_3: Q600.3 R604.1 | length 15.5
  Top Layer w0.335: 31.45,5.37 31.45,4.174 32.824,2.8 41.276,2.8 41.848,3.372 41.944,3.372 42.126,3.554 Q600.3@42.126,3.65 42.126,3.746 41.944,3.928 41.848,3.928 41.376,4.4 R604.1@39.826,4.4
NetQ601_1: Q601.1 R609.2 R610.2 | length 3.1
  Top Layer w0.335: Q601.1@45.826,5.524 45.863,5.562 45.863,6.963 R610.2@45.901,7 ; R610.2@45.901,7 R609.2@45.901,8.6 R609.2@45.914,8.613
NetQ601_3: Q601.3 R605.1 | length 21.8
  Top Layer w0.335: 29.25,5.37 29.25,3.9 31.35,1.8 43.352,1.8 44.898,3.346 44.994,3.346 45.176,3.528 Q601.3@45.176,3.624 45.176,3.724 45.852,4.4 R605.1@47.526,4.4
NetR114_2: 
NetR115_1: 
NetR121_2: R121.2 | length 0
  Top Layer w0.335: R121.2@84.55,51.082 R121.2@84.562,51.094
NetR400_1: R400.1 U400.4 | length 2.3
  Top Layer w0.335: U400.4@15.75,69.45 15.815,69.385 R400.1@18.043,69.385
NetR401_1: R401.1 R403.2 U400.3 | length 4.6
  Top Layer w0.335: U400.3@15.75,66.8 15.75,67.05 16.925,68.225 R401.1@18.1,68.225 R403.2@19.6,68.225
NetR404_1: R404.1 U402.45 | length 3.9
  Top Layer w0.2: R404.1@22.044,58.687 22.044,58.049 22.681,57.412 23.588,57.412 24.294,56.706 U402.45@24.294,56.237
NetR405_1: R405.1 U402.35 | length 5.3
  Top Layer w0.2: U402.35@28.294,55.037 29.054,55.037 31.046,57.028 R405.1@31.046,58.714
NetR407_1: R407.1 U402.46 | length 6.9
  Top Layer w0.2: R407.1@21.344,61.512 21.344,58.187 22.524,57.007 23.469,57.007 23.894,56.582 U402.46@23.894,56.237
NetR408_1: R408.1 U402.43 | length 2.8
  Top Layer w0.2: R408.1@23.634,58.412 25.094,56.952 U402.43@25.094,56.237
NetR409_1: R409.1 U402.41 | length 2.8
  Top Layer w0.2: R409.1@25.044,58.687 25.044,58.049 25.894,57.199 U402.41@25.894,56.237
NetR410_1: R410.1 U402.39 | length 2.5
  Top Layer w0.2: R410.1@26.544,58.687 26.694,58.537 U402.39@26.694,56.237
NetR411_1: R411.1 U402.37 | length 2.7
  Top Layer w0.2: U402.37@27.494,56.237 27.494,57.16 28.044,57.709 R411.1@28.044,58.687
NetR412_1: R412.1 U402.44 | length 6.4
  Top Layer w0.2: R412.1@22.793,61.512 22.793,58.188 23.199,57.782 23.741,57.782 24.694,56.829 U402.44@24.694,56.237
NetR413_1: R413.1 U402.42 | length 5.8
  Top Layer w0.2: R413.1@24.294,61.512 24.294,58.275 25.494,57.075 U402.42@25.494,56.237
NetR414_1: R414.1 U402.40 | length 5.5
  Top Layer w0.2: R414.1@25.8,61.512 25.8,57.817 26.294,57.322 U402.40@26.294,56.237
NetR415_1: R415.1 U402.38 | length 5.4
  Top Layer w0.2: U402.38@27.094,56.237 27.094,57.516 27.288,57.709 R415.1@27.288,61.512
